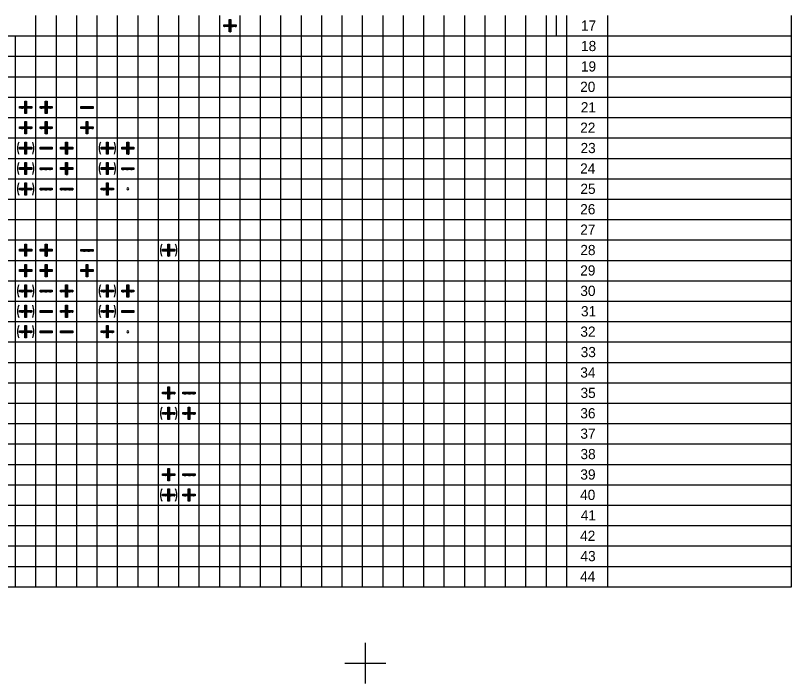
# Model space of a CAD drawing. Extents: x 2216 to 3066, y -348 to -41.
# Drawn here: x 2554.9 to 2744.9, y -348.3 to -184.6 of the extents above; entities that cross this region are included whole.
import ezdxf

# ---------------------------------------------------------------- set-up
doc = ezdxf.new("R2010")
doc.units = 0
doc.layers.add('překresleno', color=7, linetype='Continuous')
doc.layers.add('Vrstva 60', color=7, linetype='Continuous')

# ---------------------------------------------------------------- blocks, each defined once
blk = doc.blocks.new('_X0')
for p, q in [((2.28, 3.6), (2.67, 4)), ((2.28, 3.69), (2.58, 4)), ((2.28, 3.78), (2.5, 4)), ((2.28, 3.87), (2.41, 4)), ((2.28, 3.96), (2.32, 4)), ((2.28, 3.52), (2.72, 3.96)), ((2.28, 3.43), (2.72, 3.87)), ((1, 2.33), (1.4, 2.72)), ((1, 2.42), (1.31, 2.72)), ((1, 2.5), (1.22, 2.72)), ((1, 2.59), (1.13, 2.72)), ((1, 2.68), (1.04, 2.72)), ((1.04, 2.28), (1.48, 2.72)), ((1.13, 2.28), (1.57, 2.72)), ((1.22, 2.28), (1.66, 2.72)), ((1.31, 2.28), (1.75, 2.72)), ((1.39, 2.28), (1.84, 2.72)), ((1.48, 2.28), (1.93, 2.72)), ((1.57, 2.28), (2.01, 2.72)), ((1.66, 2.28), (2.1, 2.72)), ((1.75, 2.28), (2.19, 2.72)), ((1.84, 2.28), (2.72, 3.17)), ((1.92, 2.28), (2.72, 3.08)), ((2.01, 2.28), (2.72, 2.99)), ((2.1, 2.28), (2.72, 2.9)), ((2.19, 2.28), (2.72, 2.81)), ((2.28, 3.34), (2.72, 3.78)), ((2.28, 3.25), (2.72, 3.7)), ((2.28, 3.16), (2.72, 3.61)), ((2.28, 3.07), (2.72, 3.52)), ((2.28, 2.99), (2.72, 3.43)), ((2.28, 2.9), (2.72, 3.34)), ((2.28, 2.81), (2.72, 3.25)), ((2.28, 2.28), (2.72, 2.72)), ((2.28, 2.19), (2.81, 2.72)), ((2.28, 2.1), (2.9, 2.72)), ((2.28, 2.01), (2.99, 2.72)), ((2.28, 1.93), (3.08, 2.72)), ((2.28, 1.84), (3.16, 2.72)), ((2.28, 1.75), (2.72, 2.19)), ((2.28, 1.66), (2.72, 2.1)), ((2.28, 1.57), (2.72, 2.02)), ((2.28, 1.48), (2.72, 1.93)), ((2.81, 2.28), (3.25, 2.72)), ((2.9, 2.28), (3.34, 2.72)), ((2.99, 2.28), (3.43, 2.72)), ((3.07, 2.28), (3.52, 2.72)), ((3.16, 2.28), (3.61, 2.72)), ((3.25, 2.28), (3.69, 2.72)), ((3.34, 2.28), (3.78, 2.72)), ((3.43, 2.28), (3.87, 2.72)), ((3.52, 2.28), (3.96, 2.72)), ((3.6, 2.28), (4, 2.68)), ((3.69, 2.28), (4, 2.59)), ((3.78, 2.28), (4, 2.5)), ((3.87, 2.28), (4, 2.41)), ((3.96, 2.28), (4, 2.32)), ((2.28, 1.4), (2.72, 1.84)), ((2.28, 1.31), (2.72, 1.75)), ((2.28, 1.22), (2.72, 1.66)), ((2.28, 1.13), (2.72, 1.57)), ((2.28, 1.04), (2.72, 1.49)), ((2.33, 1), (2.72, 1.4)), ((2.42, 1), (2.72, 1.31)), ((2.5, 1), (2.72, 1.22)), ((2.59, 1), (2.72, 1.13)), ((2.68, 1), (2.72, 1.04))]:
    blk.add_line(p, q)
blk = doc.blocks.new('ZT82')
for p, q in [((2.5, 4), (2.5, 1)), ((1, 2.5), (4, 2.5))]:
    blk.add_line(p, q)
blk.add_lwpolyline([(2.28, 4), (2.72, 4), (2.72, 2.72), (4, 2.72), (4, 2.28), (2.72, 2.28), (2.72, 1), (2.28, 1), (2.28, 2.28), (1, 2.28), (1, 2.72), (2.28, 2.72)], close=True)
blk.add_blockref('_X0', (0, 0))
blk = doc.blocks.new('_X2')
for p, q in [((1, 2.33), (1.4, 2.73)), ((1, 2.41), (1.31, 2.73)), ((1, 2.5), (1.22, 2.73)), ((1, 2.59), (1.14, 2.73)), ((1, 2.68), (1.05, 2.73)), ((1.04, 2.28), (1.49, 2.73)), ((1.13, 2.28), (1.58, 2.73)), ((1.21, 2.28), (1.67, 2.73)), ((1.3, 2.28), (1.75, 2.73)), ((1.39, 2.28), (1.84, 2.73)), ((1.48, 2.28), (1.93, 2.73)), ((1.57, 2.28), (2.02, 2.73)), ((1.66, 2.28), (2.11, 2.73)), ((1.75, 2.28), (2.2, 2.73)), ((1.83, 2.28), (2.28, 2.73)), ((1.92, 2.28), (2.37, 2.73)), ((2.01, 2.28), (2.46, 2.73)), ((2.1, 2.28), (2.55, 2.73)), ((2.19, 2.28), (2.64, 2.73)), ((2.28, 2.28), (2.73, 2.73)), ((2.36, 2.28), (2.81, 2.73)), ((2.45, 2.28), (2.9, 2.73)), ((2.54, 2.28), (2.99, 2.73)), ((2.63, 2.28), (3.08, 2.73)), ((2.72, 2.28), (3.17, 2.73)), ((2.81, 2.28), (3.26, 2.73)), ((2.89, 2.28), (3.34, 2.73)), ((2.98, 2.28), (3.43, 2.73)), ((3.07, 2.28), (3.52, 2.73)), ((3.16, 2.28), (3.61, 2.73)), ((3.25, 2.28), (3.7, 2.73)), ((3.34, 2.28), (3.79, 2.73)), ((3.42, 2.28), (3.88, 2.73)), ((3.51, 2.28), (3.96, 2.73)), ((3.6, 2.28), (4, 2.67)), ((3.69, 2.28), (4, 2.59)), ((3.78, 2.28), (4, 2.5)), ((3.87, 2.28), (4, 2.41)), ((3.96, 2.28), (4, 2.32))]:
    blk.add_line(p, q)
blk = doc.blocks.new('ZT81')
blk.add_line((1, 2.5), (4, 2.5))
blk.add_lwpolyline([(1, 2.73), (4, 2.73), (4, 2.28), (1, 2.28)], close=True)
blk.add_blockref('_X2', (0, 0))
blk = doc.blocks.new('_X5')
for p, q in [((2.28, 3.6), (2.67, 4)), ((2.28, 3.69), (2.58, 4)), ((2.28, 3.78), (2.5, 4)), ((2.28, 3.87), (2.41, 4)), ((2.28, 3.96), (2.32, 4)), ((2.28, 3.51), (2.72, 3.96)), ((2.28, 3.43), (2.72, 3.87)), ((1, 2.33), (1.4, 2.72)), ((1, 2.41), (1.31, 2.72)), ((1, 2.5), (1.22, 2.72)), ((1, 2.59), (1.13, 2.72)), ((1, 2.68), (1.04, 2.72)), ((1.04, 2.28), (1.48, 2.72)), ((1.13, 2.28), (1.57, 2.72)), ((1.22, 2.28), (1.66, 2.72)), ((1.31, 2.28), (1.75, 2.72)), ((1.39, 2.28), (1.84, 2.72)), ((1.48, 2.28), (1.93, 2.72)), ((1.57, 2.28), (2.01, 2.72)), ((1.66, 2.28), (2.1, 2.72)), ((1.75, 2.28), (2.19, 2.72)), ((1.84, 2.28), (2.72, 3.16)), ((1.92, 2.28), (2.72, 3.08)), ((2.01, 2.28), (2.72, 2.99)), ((2.1, 2.28), (2.72, 2.9)), ((2.19, 2.28), (2.72, 2.81)), ((2.28, 3.34), (2.72, 3.78)), ((2.28, 3.25), (2.72, 3.69)), ((2.28, 3.16), (2.72, 3.61)), ((2.28, 3.07), (2.72, 3.52)), ((2.28, 2.98), (2.72, 3.43)), ((2.28, 2.9), (2.72, 3.34)), ((2.28, 2.81), (2.72, 3.25)), ((2.28, 2.28), (2.72, 2.72)), ((2.28, 2.19), (2.81, 2.72)), ((2.28, 2.1), (2.9, 2.72)), ((2.28, 2.01), (2.99, 2.72)), ((2.28, 1.92), (3.08, 2.72)), ((2.28, 1.84), (3.16, 2.72)), ((2.28, 1.75), (2.72, 2.19)), ((2.28, 1.66), (2.72, 2.1)), ((2.28, 1.57), (2.72, 2.01)), ((2.28, 1.48), (2.72, 1.93)), ((2.81, 2.28), (3.25, 2.72)), ((2.9, 2.28), (3.34, 2.72)), ((2.99, 2.28), (3.43, 2.72)), ((3.07, 2.28), (3.52, 2.72)), ((3.16, 2.28), (3.61, 2.72)), ((3.25, 2.28), (3.69, 2.72)), ((3.34, 2.28), (3.78, 2.72)), ((3.43, 2.28), (3.87, 2.72)), ((3.52, 2.28), (3.96, 2.72)), ((3.6, 2.28), (4, 2.67)), ((3.69, 2.28), (4, 2.59)), ((3.78, 2.28), (4, 2.5)), ((3.87, 2.28), (4, 2.41)), ((3.96, 2.28), (4, 2.32)), ((2.28, 1.39), (2.72, 1.84)), ((2.28, 1.31), (2.72, 1.75)), ((2.28, 1.22), (2.72, 1.66)), ((2.28, 1.13), (2.72, 1.57)), ((2.28, 1.04), (2.72, 1.48)), ((2.33, 1), (2.72, 1.4)), ((2.42, 1), (2.72, 1.31)), ((2.5, 1), (2.72, 1.22)), ((2.59, 1), (2.72, 1.13)), ((2.68, 1), (2.72, 1.04))]:
    blk.add_line(p, q)
blk = doc.blocks.new('ZT86')
for p, q in [((2.5, 4), (2.5, 1)), ((1, 2.5), (4, 2.5))]:
    blk.add_line(p, q)
blk.add_lwpolyline([(2.28, 4), (2.72, 4), (2.72, 2.72), (4, 2.72), (4, 2.28), (2.72, 2.28), (2.72, 1), (2.28, 1), (2.28, 2.28), (1, 2.28), (1, 2.72), (2.28, 2.72)], close=True)
for centre, start, end in [((4.5, 2.5), 157.9757, 202.0243), ((0.5, 2.5), 337.9757, 22.0243)]:
    blk.add_arc(centre, 4, start, end)
blk.add_blockref('_X5', (0, 0))
blk = doc.blocks.new('ZT87')
for start, end in [(0, 180), (180, 0)]:
    blk.add_arc((2.5, 2.5), 0.25, start, end)

msp = doc.modelspace()

# ---------------------------------------------------------------- linework, layer by layer
at = {"layer": 'překresleno'}
for p, q in [((2559.89, -189.57), (2559.89, -184.57)), ((2564.89, -189.57), (2564.89, -184.57)), ((2569.89, -189.57), (2569.89, -184.57)), ((2574.89, -189.57), (2574.89, -184.57)), ((2579.89, -189.57), (2579.89, -184.57)), ((2584.89, -189.57), (2584.89, -184.57)), ((2589.89, -189.57), (2589.89, -184.57)), ((2594.89, -189.57), (2594.89, -184.57)), ((2599.89, -189.57), (2599.89, -184.57)), ((2604.89, -189.57), (2604.89, -184.57)), ((2609.89, -189.57), (2609.89, -184.57)), ((2614.89, -189.57), (2614.89, -184.57)), ((2619.89, -189.57), (2619.89, -184.57)), ((2624.89, -189.57), (2624.89, -184.57)), ((2629.89, -189.57), (2629.89, -184.57)), ((2634.89, -189.57), (2634.89, -184.57)), ((2639.89, -189.57), (2639.89, -184.57)), ((2644.89, -189.57), (2644.89, -184.57)), ((2649.89, -189.57), (2649.89, -184.57)), ((2654.89, -189.57), (2654.89, -184.57)), ((2659.89, -189.57), (2659.89, -184.57)), ((2664.89, -189.57), (2664.89, -184.57)), ((2669.89, -189.57), (2669.89, -184.57)), ((2674.89, -189.57), (2674.89, -184.57)), ((2679.89, -189.57), (2679.89, -184.57)), ((2684.89, -189.57), (2684.89, -184.57)), ((2687.39, -189.57), (2687.39, -184.57)), ((2689.89, -189.57), (2689.89, -184.57)), ((2699.89, -189.57), (2699.89, -184.57)), ((2744.9, -189.57), (2744.9, -184.57)), ((2519.89, -189.57), (2554.89, -189.57)), ((2554.89, -204.57), (2554.89, -189.57)), ((2554.89, -189.57), (2689.89, -189.57)), ((2559.89, -204.57), (2559.89, -189.57)), ((2564.89, -204.57), (2564.89, -189.57)), ((2569.89, -204.57), (2569.89, -189.57)), ((2574.89, -204.57), (2574.89, -189.57)), ((2579.89, -204.57), (2579.89, -189.57)), ((2584.89, -204.57), (2584.89, -189.57)), ((2589.89, -204.57), (2589.89, -189.57)), ((2594.89, -204.57), (2594.89, -189.57)), ((2599.89, -204.57), (2599.89, -189.57)), ((2604.89, -204.57), (2604.89, -189.57)), ((2609.89, -204.57), (2609.89, -189.57)), ((2614.89, -204.57), (2614.89, -189.57)), ((2619.89, -204.57), (2619.89, -189.57)), ((2624.89, -204.57), (2624.89, -189.57)), ((2629.89, -204.57), (2629.89, -189.57)), ((2634.89, -204.57), (2634.89, -189.57)), ((2639.89, -204.57), (2639.89, -189.57)), ((2644.89, -204.57), (2644.89, -189.57)), ((2649.89, -204.57), (2649.89, -189.57)), ((2654.89, -204.57), (2654.89, -189.57)), ((2659.89, -204.57), (2659.89, -189.57)), ((2664.89, -204.57), (2664.89, -189.57)), ((2669.89, -204.57), (2669.89, -189.57)), ((2674.89, -204.57), (2674.89, -189.57)), ((2679.89, -204.57), (2679.89, -189.57)), ((2684.89, -204.57), (2684.89, -189.57)), ((2689.89, -204.57), (2689.89, -189.57)), ((2689.9, -189.57), (2699.89, -189.57)), ((2699.89, -204.57), (2699.89, -189.57)), ((2699.89, -189.57), (2744.9, -189.57)), ((2744.89, -204.57), (2744.89, -189.57)), ((2519.89, -194.57), (2554.89, -194.57)), ((2554.89, -194.57), (2689.89, -194.57)), ((2689.9, -194.57), (2699.89, -194.57)), ((2699.89, -194.57), (2744.9, -194.57)), ((2519.89, -199.57), (2554.89, -199.57)), ((2554.89, -199.57), (2689.89, -199.57)), ((2689.9, -199.57), (2699.89, -199.57)), ((2699.89, -199.57), (2744.9, -199.57)), ((2519.89, -204.57), (2554.89, -204.57)), ((2554.89, -239.57), (2554.89, -204.57)), ((2554.89, -204.57), (2689.89, -204.57)), ((2559.89, -239.57), (2559.89, -204.57)), ((2564.89, -239.57), (2564.89, -204.57)), ((2569.89, -239.57), (2569.89, -204.57)), ((2574.89, -239.57), (2574.89, -204.57)), ((2579.89, -239.57), (2579.89, -204.57)), ((2584.89, -239.57), (2584.89, -204.57)), ((2589.89, -239.57), (2589.89, -204.57)), ((2594.89, -239.57), (2594.89, -204.57)), ((2599.89, -239.57), (2599.89, -204.57)), ((2604.89, -239.57), (2604.89, -204.57)), ((2609.89, -239.57), (2609.89, -204.57)), ((2614.89, -239.57), (2614.89, -204.57)), ((2619.89, -239.57), (2619.89, -204.57)), ((2624.89, -239.57), (2624.89, -204.57)), ((2629.89, -239.57), (2629.89, -204.57)), ((2634.89, -239.57), (2634.89, -204.57)), ((2639.89, -239.57), (2639.89, -204.57)), ((2644.89, -239.57), (2644.89, -204.57)), ((2649.89, -239.57), (2649.89, -204.57)), ((2654.89, -239.57), (2654.89, -204.57)), ((2659.89, -239.57), (2659.89, -204.57)), ((2664.89, -239.57), (2664.89, -204.57)), ((2669.89, -239.57), (2669.89, -204.57)), ((2674.89, -239.57), (2674.89, -204.57)), ((2679.89, -239.57), (2679.89, -204.57)), ((2684.89, -239.57), (2684.89, -204.57)), ((2689.89, -239.57), (2689.89, -204.57)), ((2689.89, -204.57), (2699.89, -204.57)), ((2699.89, -239.57), (2699.89, -204.57)), ((2699.89, -204.57), (2744.89, -204.57)), ((2744.89, -239.57), (2744.89, -204.57)), ((2519.89, -209.57), (2554.89, -209.57)), ((2554.89, -209.57), (2689.89, -209.57)), ((2689.89, -209.57), (2699.89, -209.57)), ((2699.89, -209.57), (2744.89, -209.57)), ((2519.89, -214.57), (2554.89, -214.57)), ((2554.89, -214.57), (2689.89, -214.57)), ((2689.89, -214.57), (2699.89, -214.57)), ((2699.89, -214.57), (2744.89, -214.57)), ((2519.89, -219.57), (2554.89, -219.57)), ((2554.89, -219.57), (2689.89, -219.57)), ((2689.89, -219.57), (2699.89, -219.57)), ((2699.89, -219.57), (2744.89, -219.57)), ((2519.89, -224.57), (2554.89, -224.57)), ((2554.89, -224.57), (2689.89, -224.57)), ((2689.89, -224.57), (2699.89, -224.57)), ((2699.89, -224.57), (2744.89, -224.57)), ((2519.89, -229.57), (2554.89, -229.57)), ((2554.89, -229.57), (2689.89, -229.57)), ((2689.89, -229.57), (2699.89, -229.57)), ((2699.89, -229.57), (2744.89, -229.57)), ((2519.89, -234.57), (2554.89, -234.57)), ((2554.89, -234.57), (2689.89, -234.57)), ((2689.89, -234.57), (2699.89, -234.57)), ((2699.89, -234.57), (2744.89, -234.57)), ((2519.89, -239.57), (2554.89, -239.57)), ((2554.89, -274.57), (2554.89, -239.57)), ((2554.89, -239.57), (2689.89, -239.57)), ((2559.89, -274.57), (2559.89, -239.57)), ((2564.89, -274.57), (2564.89, -239.57)), ((2569.89, -274.57), (2569.89, -239.57)), ((2574.89, -274.57), (2574.89, -239.57)), ((2579.89, -274.57), (2579.89, -239.57)), ((2584.89, -274.57), (2584.89, -239.57)), ((2589.89, -274.57), (2589.89, -239.57)), ((2594.89, -274.57), (2594.89, -239.57)), ((2599.89, -274.57), (2599.89, -239.57)), ((2604.89, -274.57), (2604.89, -239.57)), ((2609.89, -274.57), (2609.89, -239.57)), ((2614.89, -274.57), (2614.89, -239.57)), ((2619.89, -274.57), (2619.89, -239.57)), ((2624.89, -274.57), (2624.89, -239.57)), ((2629.89, -274.57), (2629.89, -239.57)), ((2634.89, -274.57), (2634.89, -239.57)), ((2639.89, -274.57), (2639.89, -239.57)), ((2644.89, -274.57), (2644.89, -239.57)), ((2649.89, -274.57), (2649.89, -239.57)), ((2654.89, -274.57), (2654.89, -239.57)), ((2659.89, -274.57), (2659.89, -239.57)), ((2664.89, -274.57), (2664.89, -239.57)), ((2669.89, -274.57), (2669.89, -239.57)), ((2674.89, -274.57), (2674.89, -239.57)), ((2679.89, -274.57), (2679.89, -239.57)), ((2684.89, -274.57), (2684.89, -239.57)), ((2689.89, -274.57), (2689.89, -239.57)), ((2689.89, -239.57), (2699.89, -239.57)), ((2699.89, -274.57), (2699.89, -239.57)), ((2699.89, -239.57), (2744.89, -239.57)), ((2744.89, -274.57), (2744.89, -239.57)), ((2519.89, -244.57), (2554.89, -244.57)), ((2554.89, -244.57), (2689.89, -244.57)), ((2689.9, -244.57), (2699.89, -244.57)), ((2699.89, -244.57), (2744.89, -244.57)), ((2519.89, -249.57), (2554.89, -249.57)), ((2554.89, -249.57), (2689.89, -249.57)), ((2689.9, -249.57), (2699.89, -249.57)), ((2699.89, -249.57), (2744.89, -249.57)), ((2519.89, -254.57), (2554.89, -254.57)), ((2554.89, -254.57), (2689.89, -254.57)), ((2689.9, -254.57), (2699.89, -254.57)), ((2699.89, -254.57), (2744.89, -254.57)), ((2519.89, -259.57), (2554.89, -259.57)), ((2554.89, -259.57), (2689.89, -259.57)), ((2689.9, -259.57), (2699.89, -259.57)), ((2699.89, -259.57), (2744.89, -259.57)), ((2519.89, -264.57), (2554.89, -264.57)), ((2554.89, -264.57), (2689.89, -264.57)), ((2689.9, -264.57), (2699.89, -264.57)), ((2699.89, -264.57), (2744.89, -264.57)), ((2519.89, -269.57), (2554.89, -269.57)), ((2554.89, -269.57), (2689.89, -269.57)), ((2689.9, -269.57), (2699.89, -269.57)), ((2699.89, -269.57), (2744.89, -269.57)), ((2519.89, -274.57), (2554.89, -274.57)), ((2554.89, -294.57), (2554.89, -274.57)), ((2554.89, -274.57), (2689.89, -274.57)), ((2559.89, -294.57), (2559.89, -274.57)), ((2564.89, -294.57), (2564.89, -274.57)), ((2569.89, -294.57), (2569.89, -274.57)), ((2574.89, -294.57), (2574.89, -274.57)), ((2579.89, -294.57), (2579.89, -274.57)), ((2584.89, -294.57), (2584.89, -274.57)), ((2589.89, -294.57), (2589.89, -274.57)), ((2594.89, -294.57), (2594.89, -274.57)), ((2599.89, -294.57), (2599.89, -274.57)), ((2604.89, -294.57), (2604.89, -274.57)), ((2609.89, -294.57), (2609.89, -274.57)), ((2614.89, -294.57), (2614.89, -274.57)), ((2619.89, -294.57), (2619.89, -274.57)), ((2624.89, -294.57), (2624.89, -274.57)), ((2629.89, -294.57), (2629.89, -274.57)), ((2634.89, -294.57), (2634.89, -274.57)), ((2639.89, -294.57), (2639.89, -274.57)), ((2644.89, -294.57), (2644.89, -274.57)), ((2649.89, -294.57), (2649.89, -274.57)), ((2654.89, -294.57), (2654.89, -274.57)), ((2659.89, -294.57), (2659.89, -274.57)), ((2664.89, -294.57), (2664.89, -274.57)), ((2669.89, -294.57), (2669.89, -274.57)), ((2674.89, -294.57), (2674.89, -274.57)), ((2679.89, -294.57), (2679.89, -274.57)), ((2684.89, -294.57), (2684.89, -274.57)), ((2689.89, -294.57), (2689.89, -274.57)), ((2689.9, -274.57), (2699.89, -274.57)), ((2699.89, -294.57), (2699.89, -274.57)), ((2699.89, -274.57), (2744.89, -274.57)), ((2744.89, -294.57), (2744.89, -274.57)), ((2519.89, -279.57), (2554.89, -279.57)), ((2554.89, -279.57), (2689.89, -279.57)), ((2689.9, -279.57), (2699.89, -279.57)), ((2699.89, -279.57), (2744.89, -279.57)), ((2519.89, -284.57), (2554.89, -284.57)), ((2554.89, -284.57), (2689.89, -284.57)), ((2689.9, -284.57), (2699.89, -284.57)), ((2699.89, -284.57), (2744.89, -284.57)), ((2519.89, -289.57), (2554.89, -289.57)), ((2554.89, -289.57), (2689.89, -289.57)), ((2689.9, -289.57), (2699.89, -289.57)), ((2699.89, -289.57), (2744.89, -289.57)), ((2519.89, -294.57), (2554.89, -294.57)), ((2554.89, -324.57), (2554.89, -294.57)), ((2554.89, -294.57), (2689.89, -294.57)), ((2559.89, -324.57), (2559.89, -294.57)), ((2564.89, -324.57), (2564.89, -294.57)), ((2569.89, -324.57), (2569.89, -294.57)), ((2574.89, -324.57), (2574.89, -294.57)), ((2579.89, -324.57), (2579.89, -294.57)), ((2584.89, -324.57), (2584.89, -294.57)), ((2589.89, -324.57), (2589.89, -294.57)), ((2594.89, -324.57), (2594.89, -294.57)), ((2599.89, -324.57), (2599.89, -294.57)), ((2604.89, -324.57), (2604.89, -294.57)), ((2609.89, -324.57), (2609.89, -294.57)), ((2614.89, -324.57), (2614.89, -294.57)), ((2619.89, -324.57), (2619.89, -294.57)), ((2624.89, -324.57), (2624.89, -294.57)), ((2629.89, -324.57), (2629.89, -294.57)), ((2634.89, -324.57), (2634.89, -294.57)), ((2639.89, -324.57), (2639.89, -294.57)), ((2644.89, -324.57), (2644.89, -294.57)), ((2649.89, -324.57), (2649.89, -294.57)), ((2654.89, -324.57), (2654.89, -294.57)), ((2659.89, -324.57), (2659.89, -294.57)), ((2664.89, -324.57), (2664.89, -294.57)), ((2669.89, -324.57), (2669.89, -294.57)), ((2674.89, -324.57), (2674.89, -294.57)), ((2679.89, -324.57), (2679.89, -294.57)), ((2684.89, -324.57), (2684.89, -294.57)), ((2689.89, -324.57), (2689.89, -294.57)), ((2689.89, -294.57), (2699.89, -294.57)), ((2699.89, -324.57), (2699.89, -294.57)), ((2699.89, -294.57), (2744.89, -294.57)), ((2744.89, -324.57), (2744.89, -294.57)), ((2519.89, -299.57), (2554.89, -299.57)), ((2554.89, -299.57), (2689.89, -299.57)), ((2689.89, -299.57), (2699.89, -299.57)), ((2699.89, -299.57), (2744.89, -299.57)), ((2519.89, -304.57), (2554.89, -304.57)), ((2554.89, -304.57), (2689.89, -304.57)), ((2689.89, -304.57), (2699.89, -304.57)), ((2699.89, -304.57), (2744.89, -304.57)), ((2519.89, -309.57), (2554.89, -309.57)), ((2554.89, -309.57), (2689.89, -309.57)), ((2689.89, -309.57), (2699.89, -309.57)), ((2699.89, -309.57), (2744.89, -309.57)), ((2519.89, -314.57), (2554.89, -314.57)), ((2554.89, -314.57), (2689.89, -314.57)), ((2689.89, -314.57), (2699.89, -314.57)), ((2699.89, -314.57), (2744.89, -314.57)), ((2519.89, -319.57), (2554.89, -319.57)), ((2554.89, -319.57), (2689.89, -319.57)), ((2689.89, -319.57), (2699.89, -319.57)), ((2699.89, -319.57), (2744.89, -319.57)), ((2519.89, -324.57), (2554.89, -324.57)), ((2554.89, -324.57), (2689.89, -324.57)), ((2689.89, -324.57), (2699.89, -324.57)), ((2699.89, -324.57), (2744.89, -324.57))]:
    msp.add_line(p, q, dxfattribs=at)
at = {"layer": 'Vrstva 60'}
for p, q in [((2640.56, -348.27), (2640.56, -338.27)), ((2635.56, -343.27), (2645.56, -343.27))]:
    msp.add_line(p, q, dxfattribs=at)

# ---------------------------------------------------------------- block references
at = {"layer": 'překresleno'}
for name, p in [('ZT82', (2604.89, -189.57)), ('ZT82', (2554.89, -209.57)), ('ZT82', (2559.89, -209.57)), ('ZT81', (2569.89, -209.6)), ('ZT82', (2554.89, -214.57)), ('ZT82', (2559.89, -214.57)), ('ZT82', (2569.89, -214.57)), ('ZT86', (2554.89, -219.57)), ('ZT82', (2564.89, -219.57)), ('ZT86', (2574.89, -219.57)), ('ZT82', (2579.89, -219.57)), ('ZT81', (2559.89, -219.6)), ('ZT86', (2554.89, -224.57)), ('ZT81', (2559.89, -224.6)), ('ZT82', (2564.89, -224.57)), ('ZT86', (2574.89, -224.57)), ('ZT81', (2579.89, -224.6)), ('ZT86', (2554.89, -229.57)), ('ZT82', (2574.89, -229.57)), ('ZT81', (2559.89, -229.6)), ('ZT81', (2564.89, -229.6)), ('ZT87', (2579.89, -229.57)), ('ZT82', (2554.89, -244.57)), ('ZT82', (2559.89, -244.57)), ('ZT86', (2589.89, -244.57)), ('ZT81', (2569.89, -244.6)), ('ZT82', (2554.89, -249.57)), ('ZT82', (2559.89, -249.57)), ('ZT82', (2569.89, -249.57)), ('ZT86', (2554.89, -254.57)), ('ZT82', (2564.89, -254.57)), ('ZT86', (2574.89, -254.57)), ('ZT82', (2579.89, -254.57)), ('ZT81', (2559.89, -254.6)), ('ZT86', (2554.89, -259.57)), ('ZT82', (2564.89, -259.57)), ('ZT86', (2574.89, -259.57)), ('ZT81', (2559.89, -259.6)), ('ZT81', (2579.89, -259.6)), ('ZT86', (2554.89, -264.57)), ('ZT81', (2559.89, -264.6)), ('ZT81', (2564.89, -264.6)), ('ZT82', (2574.89, -264.57)), ('ZT87', (2579.89, -264.57)), ('ZT82', (2589.89, -279.57)), ('ZT81', (2594.89, -279.6)), ('ZT86', (2589.89, -284.57)), ('ZT82', (2594.89, -284.57)), ('ZT82', (2589.89, -299.57)), ('ZT81', (2594.89, -299.6)), ('ZT86', (2589.89, -304.57)), ('ZT82', (2594.89, -304.57))]:
    msp.add_blockref(name, p, dxfattribs=at)

# ---------------------------------------------------------------- texts
for s, p in [('17', (2693.35, -188.29)), ('18', (2693.37, -193.29)), ('19', (2693.34, -198.29)), ('20', (2693.15, -203.29)), ('21', (2693.31, -208.31)), ('22', (2693.16, -213.31)), ('23', (2693.24, -218.29)), ('24', (2693.15, -223.31)), ('25', (2693.21, -228.29)), ('26', (2693.16, -233.29)), ('27', (2693.17, -238.29)), ('28', (2693.19, -243.29)), ('29', (2693.17, -248.29)), ('30', (2693.19, -253.29)), ('31', (2693.35, -258.29)), ('32', (2693.2, -263.29)), ('33', (2693.28, -268.29)), ('34', (2693.19, -273.29)), ('35', (2693.24, -278.29)), ('36', (2693.19, -283.29)), ('37', (2693.21, -288.29)), ('38', (2693.23, -293.29)), ('39', (2693.2, -298.29)), ('40', (2693.14, -303.29)), ('41', (2693.3, -308.31)), ('42', (2693.15, -313.31)), ('43', (2693.23, -318.29)), ('44', (2693.14, -323.31))]:
    msp.add_text(s, height=2.5, rotation=0.0001).set_placement(p)

doc.saveas('drawing.dxf')
